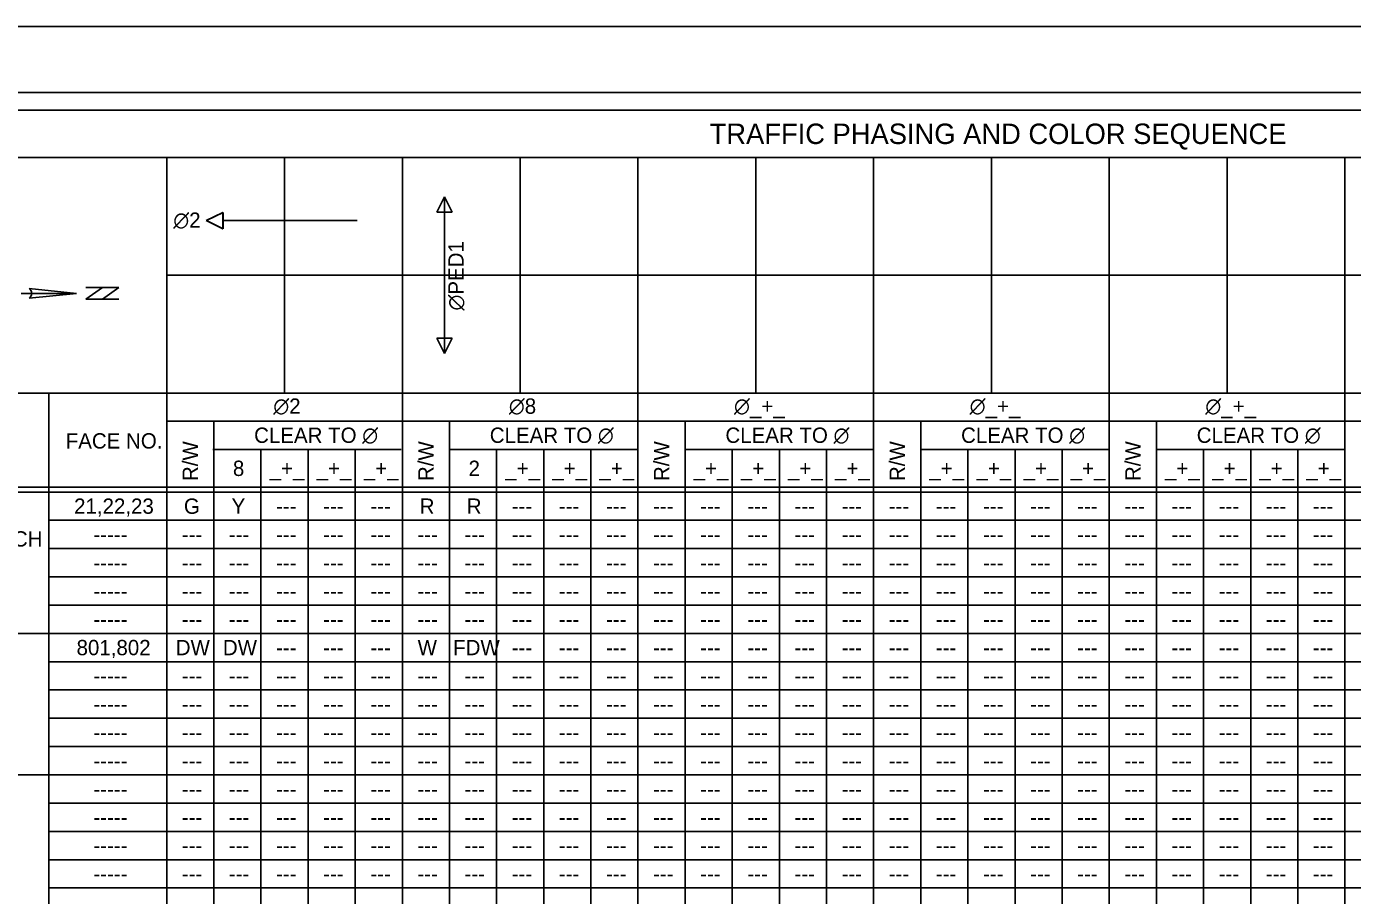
# Model space of a CAD drawing. Extents: x 10040 to 81668, y 7194 to 11018.
# Drawn here: x 10806 to 11931, y 9263 to 10000 of the extents above; entities that cross this region are included whole.
import ezdxf

# ---------------------------------------------------------------- set-up
doc = ezdxf.new("R2010")
doc.units = 0
for name, color, linetype in [('dsnCellElements', 7, 'Continuous'), ('dsnStdTable', 7, 'Continuous'), ('Level 3', 7, 'Continuous'), ('Level 4', 7, 'Continuous'), ('wetSpecialNote', 7, 'Continuous')]:
    doc.layers.add(name, color=color, linetype=linetype)

msp = doc.modelspace()

# ---------------------------------------------------------------- linework, layer by layer
at = {"layer": 'dsnCellElements'}
msp.add_lwpolyline([(10039.6, 10000), (13360.5, 10000), (13360.5, 7806.6), (10039.6, 7806.6)], close=True, dxfattribs=at)
at = {"layer": 'dsnStdTable'}
for p, q in [((10958.1, 9835.3), (10972.1, 9842.3)), ((10958.3, 9835.3), (10972.3, 9842.3)), ((10972.1, 9842.3), (10972.1, 9828.3)), ((10972.3, 9842.3), (10972.3, 9828.3)), ((10972.1, 9828.3), (10958.1, 9835.3)), ((10972.3, 9828.3), (10958.3, 9835.3)), ((10972.1, 9835.3), (11086.1, 9835.4)), ((10847.9, 9773.6), (10807.9, 9777.6)), ((10841.5, 9774), (10839.3, 9774.3)), ((10855.9, 9768.6), (10869.9, 9778.6)), ((10869.9, 9768.6), (10855.9, 9768.6)), ((10869.9, 9778.6), (10883.9, 9778.6)), ((10883.9, 9778.6), (10869.9, 9768.6))]:
    msp.add_line(p, q, dxfattribs=at)
for points in [[(10809.9, 9773.6), (10800.9, 9773.6)], [(10807.9, 9777.6), (10847.9, 9773.6)], [(10847.9, 9773.6), (10807.9, 9769.6)], [(10809.9, 9773.6), (10847.9, 9773.6)], [(10855.9, 9778.6), (10883.9, 9778.6)], [(10883.9, 9768.6), (10855.9, 9768.6)]]:
    msp.add_lwpolyline(points, dxfattribs=at)
for start, end in [(360, 53.1301), (306.8699, 360)]:
    msp.add_arc((10804.9, 9773.6), 5, start, end, dxfattribs=at)
at = {"layer": 'Level 3'}
msp.add_lwpolyline([(10132.5, 9944), (13267.5, 9944), (13267.5, 7924), (10132.5, 7924)], close=True, dxfattribs=at)
msp.add_lwpolyline([(10132.5, 9944), (13267.5, 9944), (13267.5, 7924), (10132.5, 7924)], close=True, dxfattribs=at)
at = {"layer": 'Level 4'}
for p, q in [((10664.5, 9889), (12524.5, 9889)), ((10924.5, 9889), (10924.5, 8885)), ((10924.5, 9889), (10924.5, 8885)), ((11124.5, 9889), (11124.5, 8885)), ((11124.5, 9889), (11124.5, 8885)), ((11324.5, 9889), (11324.5, 8885)), ((11324.5, 9889), (11324.5, 8885)), ((11524.5, 9889), (11524.5, 8885)), ((11524.5, 9889), (11524.5, 8885)), ((11724.5, 9889), (11724.5, 8885)), ((11724.5, 9889), (11724.5, 8885)), ((11924.5, 9889), (11924.5, 8885)), ((11924.5, 9889), (11924.5, 8885)), ((10824.5, 9689), (10824.5, 8885)), ((10964.5, 9665), (10964.5, 8885)), ((11164.5, 9665), (11164.5, 8885)), ((11364.5, 9665), (11364.5, 8885)), ((11564.5, 9665), (11564.5, 8885)), ((11764.5, 9665), (11764.5, 8885)), ((11004.5, 9641), (11004.5, 8885)), ((11044.5, 9641), (11044.5, 8885)), ((11084.5, 9641), (11084.5, 8885)), ((11204.5, 9641), (11204.5, 8885)), ((11244.5, 9641), (11244.5, 8885)), ((11284.5, 9641), (11284.5, 8885)), ((11404.5, 9641), (11404.5, 8885)), ((11444.5, 9641), (11444.5, 8885)), ((11484.5, 9641), (11484.5, 8885)), ((11604.5, 9641), (11604.5, 8885)), ((11644.5, 9641), (11644.5, 8885)), ((11684.5, 9641), (11684.5, 8885)), ((11804.5, 9641), (11804.5, 8885)), ((11844.5, 9641), (11844.5, 8885)), ((11884.5, 9641), (11884.5, 8885)), ((10664.5, 9609), (12524.5, 9609)), ((10664.5, 9605), (12524.5, 9605))]:
    msp.add_line(p, q, dxfattribs=at)
msp.add_lwpolyline([(10664.5, 9929), (12524.5, 9929), (12524.5, 8885), (10664.5, 8885)], close=True, dxfattribs=at)
at = {"layer": 'wetSpecialNote'}
for p, q in [((11024.5, 9889), (11024.5, 9689)), ((11224.5, 9889), (11224.5, 9689)), ((11424.5, 9889), (11424.5, 9689)), ((11624.5, 9889), (11624.5, 9689)), ((11824.5, 9889), (11824.5, 9689)), ((11153.7, 9842.5), (11160.2, 9855.5)), ((11160.2, 9842.5), (11160.2, 9855.5)), ((11160.2, 9855.5), (11166.7, 9842.5)), ((11160.2, 9842.5), (11153.7, 9842.5)), ((11160.2, 9842.5), (11160.2, 9789)), ((11166.7, 9842.5), (11160.2, 9842.5)), ((10924.5, 9789), (11124.5, 9789)), ((11124.5, 9789), (11324.5, 9789)), ((11160.2, 9735.5), (11160.2, 9789)), ((11324.5, 9789), (11524.5, 9789)), ((11524.5, 9789), (11724.5, 9789)), ((11724.5, 9789), (11924.5, 9789)), ((11924.5, 9789), (12124.5, 9789)), ((11153.7, 9735.5), (11160.2, 9735.5)), ((11160.2, 9722.5), (11153.7, 9735.5)), ((11166.7, 9735.5), (11160.2, 9722.5)), ((11160.2, 9735.5), (11166.7, 9735.5)), ((11160.2, 9735.5), (11160.2, 9722.5)), ((10664.5, 9689), (12524.5, 9689)), ((10924.5, 9665), (11124.5, 9665)), ((11124.5, 9665), (11324.5, 9665)), ((11324.5, 9665), (11524.5, 9665)), ((11524.5, 9665), (11724.5, 9665)), ((11724.5, 9665), (11924.5, 9665)), ((11924.5, 9665), (12124.5, 9665)), ((10963.6, 9641), (11123.6, 9641)), ((11164.5, 9641), (11324.5, 9641)), ((11364.5, 9641), (11524.5, 9641)), ((11564.5, 9641), (11724.5, 9641)), ((11764.5, 9641), (11924.5, 9641)), ((10824.5, 9581), (12524.5, 9581)), ((10824.5, 9557), (12524.5, 9557)), ((12524.5, 9533), (10824.5, 9533)), ((10824.5, 9509), (12524.5, 9509)), ((12524.5, 9485), (10664.5, 9485)), ((10824.5, 9461), (12524.5, 9461)), ((12524.5, 9437), (10824.5, 9437)), ((10824.5, 9413), (12524.5, 9413)), ((12524.5, 9389), (10824.5, 9389)), ((10664.5, 9365), (12524.5, 9365)), ((12524.5, 9341), (10824.5, 9341)), ((10824.5, 9317), (12524.5, 9317)), ((12524.5, 9293), (10824.5, 9293)), ((10824.5, 9269), (12524.5, 9269))]:
    msp.add_line(p, q, dxfattribs=at)

# ---------------------------------------------------------------- texts
at = {"layer": 'dsnStdTable'}
for s, p in [('∅2', (10930.1, 9829.2)), ('∅2', (11015, 9671.4)), ('∅8', (11214.9, 9671.4)), ('∅_+_', (11406, 9671.4)), ('∅_+_', (11606, 9671.4)), ('∅_+_', (11806, 9671.4)), ('8', (10980.7, 9618.6)), ('_+_', (11011.8, 9618.6)), ('_+_', (11051.8, 9618.6)), ('_+_', (11091.8, 9618.6)), ('2', (11180.7, 9618.6)), ('_+_', (11211.8, 9618.6)), ('_+_', (11251.8, 9618.6)), ('_+_', (11291.8, 9618.6)), ('_+_', (11371.8, 9618.6)), ('_+_', (11411.8, 9618.6)), ('_+_', (11451.8, 9618.6)), ('_+_', (11491.8, 9618.6)), ('_+_', (11571.8, 9618.6)), ('_+_', (11611.8, 9618.6)), ('_+_', (11651.8, 9618.6)), ('_+_', (11691.8, 9618.6)), ('_+_', (11771.8, 9618.6)), ('_+_', (11811.8, 9618.6)), ('_+_', (11851.8, 9618.6)), ('_+_', (11891.8, 9618.6)), ('21,22,23', (10845.9, 9586.5)), ('G', (10939.1, 9586.5)), ('Y', (10979.6, 9586.5)), ('R', (11139.2, 9586.5)), ('R', (11179.2, 9586.5)), ('---', (11017.3, 9586.5)), ('---', (11057.3, 9586.5)), ('---', (11097.3, 9586.5)), ('---', (11217.3, 9586.5)), ('---', (11257.3, 9586.5)), ('---', (11297.3, 9586.5)), ('---', (11337.3, 9586.5)), ('---', (11377.3, 9586.5)), ('---', (11417.3, 9586.5)), ('---', (11457.3, 9586.5)), ('---', (11497.3, 9586.5)), ('---', (11537.3, 9586.5)), ('---', (11577.3, 9586.5)), ('---', (11617.3, 9586.5)), ('---', (11657.3, 9586.5)), ('---', (11697.3, 9586.5)), ('---', (11737.3, 9586.5)), ('---', (11777.3, 9586.5)), ('---', (11817.3, 9586.5)), ('---', (11857.3, 9586.5)), ('---', (11897.3, 9586.5)), ('SB APPROACH', (10693.5, 9558.7)), ('-----', (10862.3, 9562.5)), ('---', (10937.3, 9562.5)), ('---', (10977.3, 9562.5)), ('---', (11017.3, 9562.5)), ('---', (11057.3, 9562.5)), ('---', (11097.3, 9562.5)), ('---', (11137.3, 9562.5)), ('---', (11177.3, 9562.5)), ('---', (11217.3, 9562.5)), ('---', (11257.3, 9562.5)), ('---', (11297.3, 9562.5)), ('---', (11337.3, 9562.5)), ('---', (11377.3, 9562.5)), ('---', (11417.3, 9562.5)), ('---', (11457.3, 9562.5)), ('---', (11497.3, 9562.5)), ('---', (11537.3, 9562.5)), ('---', (11577.3, 9562.5)), ('---', (11617.3, 9562.5)), ('---', (11657.3, 9562.5)), ('---', (11697.3, 9562.5)), ('---', (11737.3, 9562.5)), ('---', (11777.3, 9562.5)), ('---', (11817.3, 9562.5)), ('---', (11857.3, 9562.5)), ('---', (11897.3, 9562.5)), ('-----', (10862.3, 9538.5)), ('---', (10937.3, 9538.5)), ('---', (10977.3, 9538.5)), ('---', (11017.3, 9538.5)), ('---', (11057.3, 9538.5)), ('---', (11097.3, 9538.5)), ('---', (11137.3, 9538.5)), ('---', (11177.3, 9538.5)), ('---', (11217.3, 9538.5)), ('---', (11257.3, 9538.5)), ('---', (11297.3, 9538.5)), ('---', (11337.3, 9538.5)), ('---', (11377.3, 9538.5)), ('---', (11417.3, 9538.5)), ('---', (11457.3, 9538.5)), ('---', (11497.3, 9538.5)), ('---', (11537.3, 9538.5)), ('---', (11577.3, 9538.5)), ('---', (11617.3, 9538.5)), ('---', (11657.3, 9538.5)), ('---', (11697.3, 9538.5)), ('---', (11737.3, 9538.5)), ('---', (11777.3, 9538.5)), ('---', (11817.3, 9538.5)), ('---', (11857.3, 9538.5)), ('---', (11897.3, 9538.5)), ('-----', (10862.3, 9514.5)), ('---', (10937.3, 9514.5)), ('---', (10977.3, 9514.5)), ('---', (11017.3, 9514.5)), ('---', (11057.3, 9514.5)), ('---', (11097.3, 9514.5)), ('---', (11137.3, 9514.5)), ('---', (11177.3, 9514.5)), ('---', (11217.3, 9514.5)), ('---', (11257.3, 9514.5)), ('---', (11297.3, 9514.5)), ('---', (11337.3, 9514.5)), ('---', (11377.3, 9514.5)), ('---', (11417.3, 9514.5)), ('---', (11457.3, 9514.5)), ('---', (11497.3, 9514.5)), ('---', (11537.3, 9514.5)), ('---', (11577.3, 9514.5)), ('---', (11617.3, 9514.5)), ('---', (11657.3, 9514.5)), ('---', (11697.3, 9514.5)), ('---', (11737.3, 9514.5)), ('---', (11777.3, 9514.5)), ('---', (11817.3, 9514.5)), ('---', (11857.3, 9514.5)), ('---', (11897.3, 9514.5)), ('-----', (10862.3, 9490.5)), ('---', (10937.3, 9490.5)), ('---', (10977.3, 9490.5)), ('---', (11017.3, 9490.5)), ('---', (11057.3, 9490.5)), ('---', (11097.3, 9490.5)), ('---', (11137.3, 9490.5)), ('---', (11177.3, 9490.5)), ('---', (11217.3, 9490.5)), ('---', (11257.3, 9490.5)), ('---', (11297.3, 9490.5)), ('---', (11337.3, 9490.5)), ('---', (11377.3, 9490.5)), ('---', (11417.3, 9490.5)), ('---', (11457.3, 9490.5)), ('---', (11497.3, 9490.5)), ('---', (11537.3, 9490.5)), ('---', (11577.3, 9490.5)), ('---', (11617.3, 9490.5)), ('---', (11657.3, 9490.5)), ('---', (11697.3, 9490.5)), ('---', (11737.3, 9490.5)), ('---', (11777.3, 9490.5)), ('---', (11817.3, 9490.5)), ('---', (11857.3, 9490.5)), ('---', (11897.3, 9490.5)), ('801,802', (10848, 9466.5)), ('DW', (10932.2, 9466.5)), ('DW', (10972.2, 9466.5)), ('W', (11137.5, 9466.5)), ('FDW', (11167.6, 9466.5)), ('---', (11017.3, 9466.5)), ('---', (11057.3, 9466.5)), ('---', (11097.3, 9466.5)), ('---', (11217.3, 9466.5)), ('---', (11257.3, 9466.5)), ('---', (11297.3, 9466.5)), ('---', (11337.3, 9466.5)), ('---', (11377.3, 9466.5)), ('---', (11417.3, 9466.5)), ('---', (11457.3, 9466.5)), ('---', (11497.3, 9466.5)), ('---', (11537.3, 9466.5)), ('---', (11577.3, 9466.5)), ('---', (11617.3, 9466.5)), ('---', (11657.3, 9466.5)), ('---', (11697.3, 9466.5)), ('---', (11737.3, 9466.5)), ('---', (11777.3, 9466.5)), ('---', (11817.3, 9466.5)), ('---', (11857.3, 9466.5)), ('---', (11897.3, 9466.5)), ('-----', (10862.3, 9442.5)), ('---', (10937.3, 9442.5)), ('---', (10977.3, 9442.5)), ('---', (11017.3, 9442.5)), ('---', (11057.3, 9442.5)), ('---', (11097.3, 9442.5)), ('---', (11137.3, 9442.5)), ('---', (11177.3, 9442.5)), ('---', (11217.3, 9442.5)), ('---', (11257.3, 9442.5)), ('---', (11297.3, 9442.5)), ('---', (11337.3, 9442.5)), ('---', (11377.3, 9442.5)), ('---', (11417.3, 9442.5)), ('---', (11457.3, 9442.5)), ('---', (11497.3, 9442.5)), ('---', (11537.3, 9442.5)), ('---', (11577.3, 9442.5)), ('---', (11617.3, 9442.5)), ('---', (11657.3, 9442.5)), ('---', (11697.3, 9442.5)), ('---', (11737.3, 9442.5)), ('---', (11777.3, 9442.5)), ('---', (11817.3, 9442.5)), ('---', (11857.3, 9442.5)), ('---', (11897.3, 9442.5)), ('-----', (10862.3, 9418.5)), ('---', (10937.3, 9418.5)), ('---', (10977.3, 9418.5)), ('---', (11017.3, 9418.5)), ('---', (11057.3, 9418.5)), ('---', (11097.3, 9418.5)), ('---', (11137.3, 9418.5)), ('---', (11177.3, 9418.5)), ('---', (11217.3, 9418.5)), ('---', (11257.3, 9418.5)), ('---', (11297.3, 9418.5)), ('---', (11337.3, 9418.5)), ('---', (11377.3, 9418.5)), ('---', (11417.3, 9418.5)), ('---', (11457.3, 9418.5)), ('---', (11497.3, 9418.5)), ('---', (11537.3, 9418.5)), ('---', (11577.3, 9418.5)), ('---', (11617.3, 9418.5)), ('---', (11657.3, 9418.5)), ('---', (11697.3, 9418.5)), ('---', (11737.3, 9418.5)), ('---', (11777.3, 9418.5)), ('---', (11817.3, 9418.5)), ('---', (11857.3, 9418.5)), ('---', (11897.3, 9418.5)), ('-----', (10862.3, 9394.5)), ('---', (10937.3, 9394.5)), ('---', (10977.3, 9394.5)), ('---', (11017.3, 9394.5)), ('---', (11057.3, 9394.5)), ('---', (11097.3, 9394.5)), ('---', (11137.3, 9394.5)), ('---', (11177.3, 9394.5)), ('---', (11217.3, 9394.5)), ('---', (11257.3, 9394.5)), ('---', (11297.3, 9394.5)), ('---', (11337.3, 9394.5)), ('---', (11377.3, 9394.5)), ('---', (11417.3, 9394.5)), ('---', (11457.3, 9394.5)), ('---', (11497.3, 9394.5)), ('---', (11537.3, 9394.5)), ('---', (11577.3, 9394.5)), ('---', (11617.3, 9394.5)), ('---', (11657.3, 9394.5)), ('---', (11697.3, 9394.5)), ('---', (11737.3, 9394.5)), ('---', (11777.3, 9394.5)), ('---', (11817.3, 9394.5)), ('---', (11857.3, 9394.5)), ('---', (11897.3, 9394.5)), ('-----', (10862.3, 9370.5)), ('---', (10937.3, 9370.5)), ('---', (10977.3, 9370.5)), ('---', (11017.3, 9370.5)), ('---', (11057.3, 9370.5)), ('---', (11097.3, 9370.5)), ('---', (11137.3, 9370.5)), ('---', (11177.3, 9370.5)), ('---', (11217.3, 9370.5)), ('---', (11257.3, 9370.5)), ('---', (11297.3, 9370.5)), ('---', (11337.3, 9370.5)), ('---', (11377.3, 9370.5)), ('---', (11417.3, 9370.5)), ('---', (11457.3, 9370.5)), ('---', (11497.3, 9370.5)), ('---', (11537.3, 9370.5)), ('---', (11577.3, 9370.5)), ('---', (11617.3, 9370.5)), ('---', (11657.3, 9370.5)), ('---', (11697.3, 9370.5)), ('---', (11737.3, 9370.5)), ('---', (11777.3, 9370.5)), ('---', (11817.3, 9370.5)), ('---', (11857.3, 9370.5)), ('---', (11897.3, 9370.5)), ('-----', (10862.3, 9346.5)), ('---', (10937.3, 9346.5)), ('---', (10977.3, 9346.5)), ('---', (11017.3, 9346.5)), ('---', (11057.3, 9346.5)), ('---', (11097.3, 9346.5)), ('---', (11137.3, 9346.5)), ('---', (11177.3, 9346.5)), ('---', (11217.3, 9346.5)), ('---', (11257.3, 9346.5)), ('---', (11297.3, 9346.5)), ('---', (11337.3, 9346.5)), ('---', (11377.3, 9346.5)), ('---', (11417.3, 9346.5)), ('---', (11457.3, 9346.5)), ('---', (11497.3, 9346.5)), ('---', (11537.3, 9346.5)), ('---', (11577.3, 9346.5)), ('---', (11617.3, 9346.5)), ('---', (11657.3, 9346.5)), ('---', (11697.3, 9346.5)), ('---', (11737.3, 9346.5)), ('---', (11777.3, 9346.5)), ('---', (11817.3, 9346.5)), ('---', (11857.3, 9346.5)), ('---', (11897.3, 9346.5)), ('-----', (10862.3, 9322.5)), ('---', (10937.3, 9322.5)), ('---', (10977.3, 9322.5)), ('---', (11017.3, 9322.5)), ('---', (11057.3, 9322.5)), ('---', (11097.3, 9322.5)), ('---', (11137.3, 9322.5)), ('---', (11177.3, 9322.5)), ('---', (11217.3, 9322.5)), ('---', (11257.3, 9322.5)), ('---', (11297.3, 9322.5)), ('---', (11337.3, 9322.5)), ('---', (11377.3, 9322.5)), ('---', (11417.3, 9322.5)), ('---', (11457.3, 9322.5)), ('---', (11497.3, 9322.5)), ('---', (11537.3, 9322.5)), ('---', (11577.3, 9322.5)), ('---', (11617.3, 9322.5)), ('---', (11657.3, 9322.5)), ('---', (11697.3, 9322.5)), ('---', (11737.3, 9322.5)), ('---', (11777.3, 9322.5)), ('---', (11817.3, 9322.5)), ('---', (11857.3, 9322.5)), ('---', (11897.3, 9322.5)), ('-----', (10862.3, 9298.5)), ('---', (10937.3, 9298.5)), ('---', (10977.3, 9298.5)), ('---', (11017.3, 9298.5)), ('---', (11057.3, 9298.5)), ('---', (11097.3, 9298.5)), ('---', (11137.3, 9298.5)), ('---', (11177.3, 9298.5)), ('---', (11217.3, 9298.5)), ('---', (11257.3, 9298.5)), ('---', (11297.3, 9298.5)), ('---', (11337.3, 9298.5)), ('---', (11377.3, 9298.5)), ('---', (11417.3, 9298.5)), ('---', (11457.3, 9298.5)), ('---', (11497.3, 9298.5)), ('---', (11537.3, 9298.5)), ('---', (11577.3, 9298.5)), ('---', (11617.3, 9298.5)), ('---', (11657.3, 9298.5)), ('---', (11697.3, 9298.5)), ('---', (11737.3, 9298.5)), ('---', (11777.3, 9298.5)), ('---', (11817.3, 9298.5)), ('---', (11857.3, 9298.5)), ('---', (11897.3, 9298.5)), ('-----', (10862.3, 9274.5)), ('---', (10937.3, 9274.5)), ('---', (10977.3, 9274.5)), ('---', (11017.3, 9274.5)), ('---', (11057.3, 9274.5)), ('---', (11097.3, 9274.5)), ('---', (11137.3, 9274.5)), ('---', (11177.3, 9274.5)), ('---', (11217.3, 9274.5)), ('---', (11257.3, 9274.5)), ('---', (11297.3, 9274.5)), ('---', (11337.3, 9274.5)), ('---', (11377.3, 9274.5)), ('---', (11417.3, 9274.5)), ('---', (11457.3, 9274.5)), ('---', (11497.3, 9274.5)), ('---', (11537.3, 9274.5)), ('---', (11577.3, 9274.5)), ('---', (11617.3, 9274.5)), ('---', (11657.3, 9274.5)), ('---', (11697.3, 9274.5)), ('---', (11737.3, 9274.5)), ('---', (11777.3, 9274.5)), ('---', (11817.3, 9274.5)), ('---', (11857.3, 9274.5)), ('---', (11897.3, 9274.5))]:
    msp.add_text(s, height=13, dxfattribs=at).set_placement(p)
msp.add_text('∅PED1', height=13, rotation=90, dxfattribs=at).set_placement((11176.5, 9759))
at = {"layer": 'wetSpecialNote'}
for s, height, p in [('TRAFFIC PHASING AND COLOR SEQUENCE', 17.341, (11385.3, 9900.3)), ('CLEAR TO ∅', 13, (10998.7, 9646.7)), ('CLEAR TO ∅', 13, (11198.7, 9646.7)), ('CLEAR TO ∅', 13, (11398.7, 9646.7)), ('CLEAR TO ∅', 13, (11598.7, 9646.7)), ('CLEAR TO ∅', 13, (11798.7, 9646.7)), ('FACE NO.', 13, (10838.8, 9641.9))]:
    msp.add_text(s, height=height, dxfattribs=at).set_placement(p)
for p in [(10951, 9614.3), (11151, 9614.3), (11351, 9614.3), (11551, 9614.3), (11751, 9614.3)]:
    msp.add_text('R/W', height=13, rotation=90, dxfattribs=at).set_placement(p)

doc.saveas('drawing.dxf')
